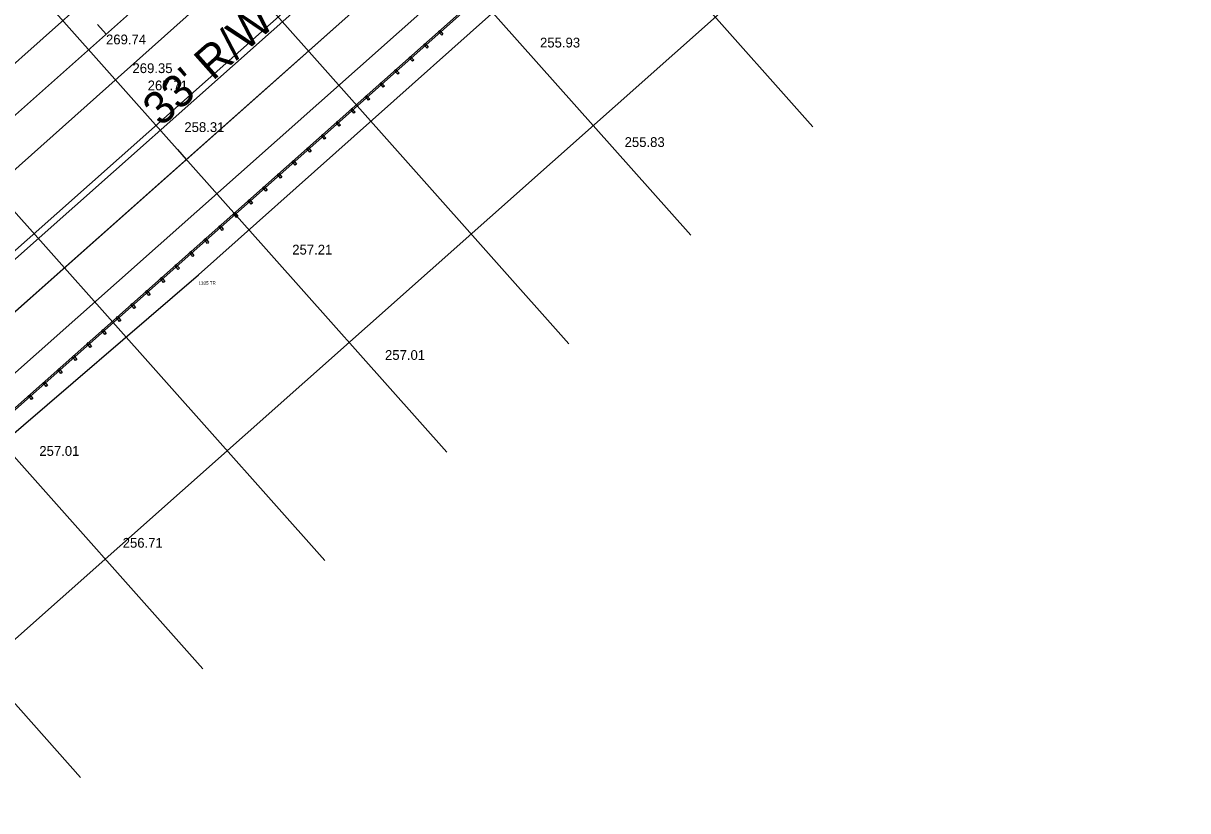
# Model space of a CAD drawing. Extents: x 49683 to 58852, y 49525 to 54803.
# Drawn here: x 53192.2 to 53548.7, y 51043.4 to 51284.7 of the extents above; entities that cross this region are included whole.
import ezdxf

# ---------------------------------------------------------------- set-up
doc = ezdxf.new("R2010")
doc.units = 0
for name, color, linetype in [('Level 1', 7, 'Continuous'), ('Level 11', 7, 'Continuous'), ('Level 13', 7, 'Continuous'), ('Level 19', 7, 'Continuous'), ('Level 20', 7, 'Continuous'), ('Level 25', 7, 'Continuous'), ('Level 27', 7, 'Continuous'), ('Level 29', 7, 'Continuous'), ('Level 3', 7, 'Continuous'), ('Level 32', 7, 'Continuous'), ('Level 33', 7, 'Continuous'), ('Level 50', 7, 'Continuous'), ('Level 61', 7, 'Continuous'), ('Level 63', 7, 'Continuous')]:
    doc.layers.add(name, color=color, linetype=linetype)

msp = doc.modelspace()

# ---------------------------------------------------------------- linework, layer by layer
at = {"layer": 'Level 1'}
for p, q in [((52544.81, 50683.3), (55534.58, 53340.86)), ((53217.61, 51281.34), (53214.95, 51284.33))]:
    msp.add_line(p, q, dxfattribs=at)
at = {"layer": 'Level 11'}
for p, q in [((53245.86, 51207.55), (53944.24, 51830.77)), ((52882.73, 50895.61), (53245.86, 51207.55))]:
    msp.add_line(p, q, dxfattribs=at)
at = {"layer": 'Level 13'}
msp.add_line((53407.7, 51406.16), (52566.74, 50658.64), dxfattribs=at)
at = {"layer": 'Level 19'}
for p, q in [((52714.15, 50773.62), (54181.77, 52078.16)), ((53242.16, 51242.96), (53239.5, 51245.95))]:
    msp.add_line(p, q, dxfattribs=at)
at = {"layer": 'Level 20'}
for p, q in [((52704.85, 50784.08), (53476.26, 51469.77)), ((52723.45, 50763.15), (53495.78, 51449.66))]:
    msp.add_line(p, q, dxfattribs=at)
at = {"layer": 'Level 27'}
for p, q in [((52953.7, 50957.11), (53467.54, 51413.86)), ((52954.03, 50956.74), (53467.88, 51413.49))]:
    msp.add_line(p, q, dxfattribs=at)
for points in [[(53320.71, 51281.33), (53320.33, 51281.01), (53319.36, 51282.16), (53319.75, 51282.48)], [(53316.22, 51277.34), (53315.84, 51277.02), (53314.88, 51278.17), (53315.26, 51278.49)], [(53311.74, 51273.36), (53311.36, 51273.04), (53310.39, 51274.19), (53310.78, 51274.51)], [(53307.26, 51269.37), (53306.87, 51269.05), (53305.91, 51270.2), (53306.29, 51270.52)], [(53302.77, 51265.38), (53302.39, 51265.06), (53301.43, 51266.21), (53301.81, 51266.53)], [(53298.29, 51261.4), (53297.9, 51261.08), (53296.94, 51262.23), (53297.33, 51262.55)], [(53293.8, 51257.41), (53293.42, 51257.09), (53292.46, 51258.24), (53292.84, 51258.56)], [(53289.32, 51253.42), (53288.93, 51253.1), (53287.97, 51254.26), (53288.36, 51254.58)], [(53284.83, 51249.44), (53284.45, 51249.12), (53283.49, 51250.27), (53283.87, 51250.59)], [(53280.35, 51245.45), (53279.97, 51245.13), (53279, 51246.28), (53279.39, 51246.6)], [(53275.86, 51241.47), (53275.48, 51241.15), (53274.52, 51242.3), (53274.9, 51242.62)], [(53271.38, 51237.48), (53271, 51237.16), (53270.03, 51238.31), (53270.42, 51238.63)], [(53266.9, 51233.49), (53266.51, 51233.17), (53265.55, 51234.32), (53265.93, 51234.65)], [(53262.41, 51229.51), (53262.03, 51229.19), (53261.07, 51230.34), (53261.45, 51230.66)], [(53257.93, 51225.52), (53257.54, 51225.2), (53256.58, 51226.35), (53256.97, 51226.67)], [(53253.44, 51221.54), (53253.06, 51221.21), (53252.1, 51222.37), (53252.48, 51222.69)], [(53248.96, 51217.55), (53248.57, 51217.23), (53247.61, 51218.38), (53248, 51218.7)], [(53244.47, 51213.56), (53244.09, 51213.24), (53243.13, 51214.39), (53243.51, 51214.71)], [(53239.99, 51209.58), (53239.61, 51209.26), (53238.64, 51210.41), (53239.03, 51210.73)], [(53235.5, 51205.59), (53235.12, 51205.27), (53234.16, 51206.42), (53234.54, 51206.74)], [(53231.02, 51201.6), (53230.64, 51201.28), (53229.67, 51202.44), (53230.06, 51202.76)], [(53226.54, 51197.62), (53226.15, 51197.3), (53225.19, 51198.45), (53225.57, 51198.77)], [(53222.05, 51193.63), (53221.67, 51193.31), (53220.71, 51194.46), (53221.09, 51194.78)], [(53217.57, 51189.65), (53217.18, 51189.33), (53216.22, 51190.48), (53216.6, 51190.8)], [(53213.08, 51185.66), (53212.7, 51185.34), (53211.74, 51186.49), (53212.12, 51186.81)], [(53208.6, 51181.67), (53208.21, 51181.35), (53207.25, 51182.5), (53207.64, 51182.82)], [(53204.11, 51177.69), (53203.73, 51177.37), (53202.77, 51178.52), (53203.15, 51178.84)], [(53199.63, 51173.7), (53199.24, 51173.38), (53198.28, 51174.53), (53198.67, 51174.85)], [(53195.14, 51169.72), (53194.76, 51169.39), (53193.8, 51170.55), (53194.18, 51170.87)]]:
    msp.add_lwpolyline(points, close=True, dxfattribs=at)
at = {"layer": 'Level 29'}
for p, q in [((52714.15, 50773.62), (54181.77, 52078.16)), ((53242.16, 51242.96), (53239.5, 51245.95))]:
    msp.add_line(p, q, dxfattribs=at)
at = {"layer": 'Level 3'}
for p, q in [((53162.5, 51248.32), (53434.09, 51489.84)), ((53179.35, 51230.72), (53449.72, 51471.81))]:
    msp.add_line(p, q, dxfattribs=at)
at = {"layer": 'Level 33'}
msp.add_line((52763.97, 50717.56), (53711.35, 51559.67), dxfattribs=at)
at = {"layer": 'Level 50'}
for p, q in [((53274.55, 51432.3), (53433.99, 51252.92)), ((53237.18, 51399.08), (53396.62, 51219.7)), ((53199.8, 51365.86), (53359.25, 51186.48)), ((53162.43, 51332.65), (53321.88, 51153.27)), ((53125.06, 51299.43), (53284.51, 51120.05)), ((53087.69, 51266.21), (53247.14, 51086.83)), ((53050.32, 51232.99), (53209.77, 51053.61))]:
    msp.add_line(p, q, dxfattribs=at)
at = {"layer": 'Level 63'}
for p, q in [((52716.81, 50794.72), (53451.1, 51447.41)), ((53460.4, 51436.95), (52726.11, 50784.25)), ((53460.4, 51436.95), (52800.86, 50850.69)), ((52810.16, 50840.23), (53469.7, 51426.49))]:
    msp.add_line(p, q, dxfattribs=at)

# ---------------------------------------------------------------- texts
at = {"layer": 'Level 25'}
msp.add_text("33' R/W FILE # 408-B", height=10, rotation=41.6333, dxfattribs=at).set_placement((53234.4, 51252.78))
at = {"layer": 'Level 32'}
for s, p in [('269.74', (53217.54, 51278.2)), ('255.93', (53350.42, 51277.24)), ('269.35', (53225.64, 51269.4)), ('267.71', (53230.3, 51264.11)), ('258.31', (53241.53, 51251.34)), ('255.83', (53376.32, 51246.76)), ('257.21', (53274.56, 51213.8)), ('257.01', (53302.96, 51181.52)), ('257.01', (53197.12, 51152.12)), ('256.71', (53222.65, 51123.97))]:
    msp.add_text(s, height=3, dxfattribs=at).set_placement(p)
at = {"layer": 'Level 61'}
msp.add_text('1335 TR', height=1, dxfattribs=at).set_placement((53245.86, 51204.55))

doc.saveas('drawing.dxf')
